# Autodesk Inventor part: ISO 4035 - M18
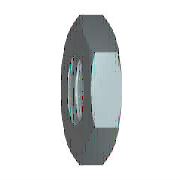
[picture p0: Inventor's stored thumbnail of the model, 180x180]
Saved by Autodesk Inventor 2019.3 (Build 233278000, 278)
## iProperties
Created: 2018-01
Part Number: ISO 4035 - M18
Material: Nerezová ocel 440C
Description: Šestihranná matice
Document SubType Name: Modeling
Standard: ISO 4035
Designer: B-hon
Standards Organization: DIN
Language: cs-CZ
Size Designation: M18
Categories: <MemberInstance><Categories><Category DisplayName="Spojovací materiál" InternalName="e4da775c-781d-43d5-af7c-5136215cf5a6" Mnemonic="FSTN"><Category DisplayName
Density: 7.75 g/cm^3
Appearance: Pololeštěná
IsCustomPart: 0
Author: B-hon
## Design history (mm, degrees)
sketch "Náčrt1"
  geometry: L1 (-15.588, 0)-(-7.794, 13.5); L2 (-7.794, 13.5)-(7.794, 13.5); L3 (7.794, 13.5)-(15.588, 0); L4 (15.588, 0)-(7.794, -13.5); L5 (7.794, -13.5)-(-7.794, -13.5); L6 (-7.794, -13.5)-(-15.588, 0); 2 further points
  constraints: 12 end point, 1 coincident, 1 horizontal, 11 other
  dimensions: "d0" = 31.17691 distance of L3.end L1.start (= 1.1547 x SW)
extrude "Těleso" new body sketch "Náčrt1" distance "d1" = 9 (= KOH); taper "d2" = 0 deg
sketch "Náčrt2"
  geometry: L1 (0, 7.794)-(0, 15.588) reference; L2 (0, 15.588)-(9, 15.588) reference; L3 (9, 7.794)-(9, 15.588) reference; L4 (-1.8, 0)-(10.8, 0) reference; L5 (1.812, 15.588)-(0, 12.45); L6 (7.188, 15.588)-(9, 12.45)
  constraints: 4 end point, 4 point on line
  dimensions: "d3" = 30 deg angle of L1 L5 (= ANG1); "d4" = 30 deg angle of L3 L6 (= ANG2); "d5" = 24.9 diameter of L5.end L4 (= SW0); "d6" = 24.9 diameter of L6.end L4 (= SW01)
revolve "Zkosení1" sketch "Náčrt2" stored, may be unused: angle "d7" = 90 deg
sketch "Náčrt3"
  geometry: 4 further points
  constraints: 1 coincident, 1 other
hole "Závit" sketch "Náčrt3" at (0, 0) diameter "d25" = 15.2937; stored, may be unused: countersink angle "d29" = 82 deg, drill point angle "d31" = 118 deg; dims "d26" = 6, "d27" = 4, "d28" = 2, "d30" = 8
workaxis "Work Axis1"
workplane "Work Plane1"
body "Solid1"
chamfer "Zkosení2" distance "d8" = 1.35316 (= -0.5 x GD1 + 0.5 x NND); stored, may be unused: angle "d9" = 30 deg, second distance "d40" = 1.35316 (= -0.5 x GD1 + 0.5 x NND)
chamfer "Zkosení3" distance "d10" = 1.35316 (= -0.5 x GD1 + 0.5 x NND); stored, may be unused: angle "d11" = 30 deg, second distance "d41" = 1.35316 (= -0.5 x GD1 + 0.5 x NND)
other parameters: "ANG1" = 30 deg [user parameter; used in 1 equation term], "ANG2" = 30 deg [user parameter; used in 1 equation term], "NND" = 18 [user parameter; used in 4 equation terms], "KOH" = 9 [user parameter; used in 1 equation term], "SW" = 27 [user parameter; used in 2 equation terms], "SW0" = 24.9 [user parameter; used in 2 equation terms], "SW01" = 24.9 (= SW0) [user parameter; used in 1 equation term], "GD1" = 15.29367 (computed from THREADDIA, PTC, TOA) [user parameter; used in 4 equation terms], "d13" = 0, "d14" = 0, "d39" = 0, "d42" = 0, "GUL" = 1.35317 (= 0.541266 x PTC) [user parameter], "TPU" = 4 (computed from PTC) [user parameter], "THREADDIA" = 18 [user parameter; used in 1 equation term], "TOA" = 30 deg [user parameter; used in 1 equation term], "PTC" = 2.5 [user parameter; used in 4 equation terms], "E0" = 31.185 (= 1.155 x SW) [user parameter], "GAL" = 1.35317 (= 0.541266 x PTC) [user parameter]
